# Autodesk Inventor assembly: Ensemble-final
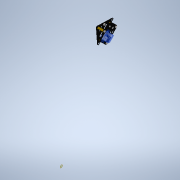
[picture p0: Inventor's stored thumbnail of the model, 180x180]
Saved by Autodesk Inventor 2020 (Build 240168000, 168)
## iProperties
Created: 2021-10
Part Number: Ensemble-final
Document SubType Name: Assembly
Designer: bruno
Mass: 18.8405 g
Surface Area: 253.631 cm^2
Volume: 12.257 cm^3
Density: 1.53711 g/cm^3
Author: bruno
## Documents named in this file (2)
- C:\Users\bruno\OneDrive\Bureau\Robot-Inventor\Robot-equillibrage\Ensemble-final.iam
- C:\Users\bruno\OneDrive\Bureau\Robot-Inventor\Robot-equillibrage\Ensemble-corps.iam
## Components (1 placed, 1 different names)
1. Ensemble-corps:1 [sub-assembly]
